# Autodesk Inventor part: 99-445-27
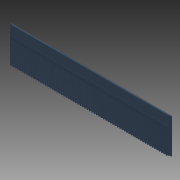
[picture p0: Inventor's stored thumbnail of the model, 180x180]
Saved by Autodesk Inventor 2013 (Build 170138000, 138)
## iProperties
Created: 2004-11
Part Number: 99-445-27
Document SubType Name: Modeling
Designer: Autodesk, Inc.
Manufacturer: Standard
Standards Organization: Custom
Description: ESD, SLOTS, LONG
Mass: 91.61 g
Surface Area: 699.021 cm^2
Volume: 91.61 cm^3
Density: 1 g/cm^3
Material: Allgemein
CAGE: 1LJX3
Dept. ID: Product Design
Description #2: ---
Finish #1: ---
Finish #2: ---
Material ID: ---
Project Number: ---
Author: Autodesk, Inc.
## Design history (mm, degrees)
sketch "Sketch1"
  geometry: L1 (-170, 37.5)-(170, 37.5); L2 (170, 37.5)-(170, -37.5); L3 (170, -37.5)-(-170, -37.5); L4 (-170, -37.5)-(-170, 37.5); 3 further points
  constraints: 8 end point, 2 midpoint, 2 parallel, 1 horizontal, 1 horizontal alignment, 1 perpendicular, 1 vertical alignment
  dimensions: "d0" = 75 distance of L3.end L1.start; "d1" = 340 distance of L1.start L1.end
extrude "Extrusion1" new body sketch "Sketch1" distance "d2" = 3; taper "d3" = 0 deg
sketch "Sketch2"
  geometry: L1 (170, -37.5)-(-170, -37.5) reference; L2 (-170, -37.5)-(-170, 10); L3 (-170, 10)-(-169.375, 17.5); L4 (-169.375, 17.5)-(-168.625, 17.5); L5 (-168.625, 17.5)-(-168, 10); L6 (-168, 10)-(-168, -37.5); L7 (-169, 17.5)-(-169, -37.5); L8 (-170, -37.5)-(-170, 37.5) reference; L9 (-170, 37.5)-(170, 37.5) reference
  constraints: 12 end point, 4 perpendicular, 3 point on line, 1 collinear, 1 midpoint, 2 other
  dimensions: "d4" = 2 distance between parallel lines of L6 L2; "d5" = 0.75 distance of L3.end L4.end; "d15" = 7.5 distance from line of L2.end L4; "d16" = 20 distance between parallel lines of L9 L4
extrude "Extrusion2" join sketch "Sketch2" distance "d8" = 2; taper "d9" = 0 deg
sketch "Sketch3"
  geometry: L1 (0, 0)-(-5, 0) reference; L2 (0, 75)-(0, 0) reference; L3 (0, 75)-(-3, 75) reference; L4 (-1.5, 75)-(-1.5, 0)
  constraints: 2 end point, 1 midpoint, 1 parallel, 1 point on line
extrude "Extrusion3" join sketch "Sketch3" distance "d13" = 3.5; taper "d14" = 0 deg
mirror "Mirror1"
body "Solid1"
pattern_linear "Rectangular Pattern1" dims "d12" = 5
